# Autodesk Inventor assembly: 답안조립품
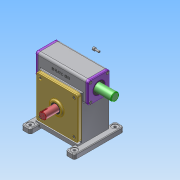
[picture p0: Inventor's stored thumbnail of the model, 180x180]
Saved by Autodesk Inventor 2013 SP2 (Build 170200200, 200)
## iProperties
Created: 2025-06
Part Number: 답안조립품
Document SubType Name: Assembly
Designer: a
Author: a
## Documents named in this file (13)
- C:\Users\a\Desktop\750603V1005\답안조립품.iam
- C:\Users\a\Desktop\750603V1005\본체.ipt
- C:\Users\a\Desktop\750603V1005\깊은 홈 볼 베어링 6209.ipt
- C:\Users\a\Desktop\750603V1005\뒷커버.ipt
- C:\Users\a\Desktop\750603V1005\앞커버.ipt
- C:\Users\a\Desktop\750603V1005\웜 샤프트.ipt
- C:\Users\a\Desktop\750603V1005\오일 실 35 55 11.ipt
- C:\Users\a\Desktop\750603V1005\오일 실 30 42 7.ipt
- C:\Users\a\Desktop\750603V1005\웜 휠 커버.ipt
- C:\Users\a\Desktop\750603V1005\웜 휠.ipt
- C:\Users\a\Desktop\750603V1005\깊은 홈 볼 베어링 6206.ipt
- C:\Users\a\Desktop\750603V1005\6각 구멍붙이 볼트 M6x12.ipt
- C:\Users\a\Desktop\750603V1005\6각 구멍붙이 볼트 M8x20.ipt
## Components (13 placed, 2 different names)
1. 6각 구멍붙이 볼트 M8x20:1
2. 6각 구멍붙이 볼트 M8x20:2
3. 6각 구멍붙이 볼트 M8x20:3
4. 6각 구멍붙이 볼트 M8x20:4
5. 6각 구멍붙이 볼트 M8x20:5
6. 6각 구멍붙이 볼트 M8x20:6
7. 6각 구멍붙이 볼트 M8x20:7
8. 6각 구멍붙이 볼트 M8x20:8
9. 6각 구멍붙이 볼트 M8x20:9
10. 6각 구멍붙이 볼트 M6x12:1
11. 6각 구멍붙이 볼트 M8x20:10
12. 6각 구멍붙이 볼트 M8x20:11
13. 6각 구멍붙이 볼트 M8x20:12
